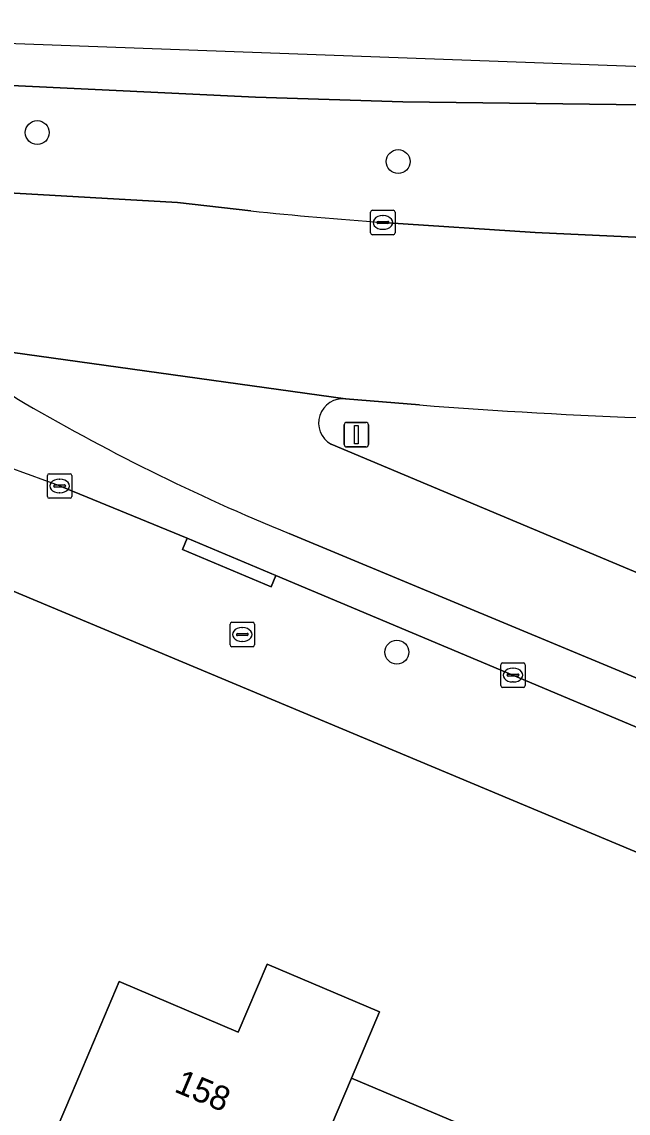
# Model space of a CAD drawing. Extents: x 162073 to 163043, y 381818 to 382561.
# Drawn here: x 162513.48 to 162538.27, y 382469.34 to 382513.97 of the extents above; entities that cross this region are included whole.
import ezdxf

# ---------------------------------------------------------------- set-up
doc = ezdxf.new("R2010")
doc.units = 0
for name, color, linetype in [('IMGEO_Boom', 7, 'Continuous'), ('IMGEO_Brandkraan', 7, 'Continuous'), ('IMGEO_Erf', 7, 'Continuous'), ('IMGEO_Fietspad_gesloten', 7, 'Continuous'), ('IMGEO_Groenvoorziening', 7, 'Continuous'), ('IMGEO_Kolk', 7, 'Continuous'), ('IMGEO_Lichtmast', 7, 'Continuous'), ('IMGEO_Pand', 7, 'Continuous'), ('IMGEO_Pand_nummerreeks', 7, 'Continuous'), ('IMGEO_Rijbaan_lokaal_gesloten', 7, 'Continuous'), ('IMGEO_Rijbaan_lokaal_open', 7, 'Continuous'), ('IMGEO_Verkeerseiland_groen', 7, 'Continuous'), ('IMGEO_Voetpad_open', 7, 'Continuous')]:
    doc.layers.add(name, color=color, linetype=linetype)

msp = doc.modelspace()

# ---------------------------------------------------------------- linework, layer by layer
at = {"layer": 'IMGEO_Boom'}
for centre in [(162514.109, 382509.442), (162528.864, 382508.257), (162528.813, 382488.194)]:
    msp.add_circle(centre, 0.489, dxfattribs=at)
at = {"layer": 'IMGEO_Brandkraan'}
for p, q in [((162521.991, 382488.49), (162521.991, 382489.342)), ((162522.066, 382489.416), (162522.918, 382489.416)), ((162522.479, 382489.196), (162522.504, 382489.196)), ((162522.992, 382489.342), (162522.992, 382488.49)), ((162522.25, 382488.91), (162522.25, 382488.922)), ((162522.688, 382488.873), (162522.29, 382488.873)), ((162522.293, 382488.959), (162522.691, 382488.959)), ((162522.502, 382488.636), (162522.477, 382488.636)), ((162522.734, 382488.922), (162522.734, 382488.91)), ((162522.918, 382488.416), (162522.066, 382488.416))]:
    msp.add_line(p, q, dxfattribs=at)
for points in [[(162521.991, 382488.49), (162521.991, 382489.342)], [(162522.066, 382489.416), (162522.918, 382489.416)], [(162522.992, 382489.342), (162522.992, 382488.49)], [(162522.918, 382488.416), (162522.066, 382488.416)]]:
    msp.add_lwpolyline(points, dxfattribs=at)
for centre, radius, start, end in [((162522.068, 382489.34), 0.0765, 91.552, 178.448), ((162522.068, 382489.34), 0.0765, 91.552, 178.448), ((162522.916, 382489.34), 0.0765, 1.552, 88.448), ((162522.916, 382489.34), 0.0765, 1.552, 88.448), ((162522.29, 382488.919), 0.0403, 85.8775, 175.7526), ((162522.287, 382488.909), 0.0366, 178.938, 274.7102), ((162522.691, 382488.916), 0.043, 264.8664, 352.4533), ((162522.695, 382488.921), 0.0386, 1.7309, 96.639), ((162522.068, 382488.492), 0.0765, 181.552, 268.448), ((162522.068, 382488.492), 0.0765, 181.552, 268.448), ((162522.916, 382488.492), 0.0765, 271.552, 358.448), ((162522.916, 382488.492), 0.0765, 271.552, 358.448)]:
    msp.add_arc(centre, radius, start, end, dxfattribs=at)
for centre, major_axis, ratio, start_param, end_param in [((162522.478, 382488.916), (-0.387, 0.002), 0.722429, 4.712389, 7.853982), ((162522.503, 382488.916), (-0.39, 0.002), 0.717154, 1.570796, 4.712389)]:
    msp.add_ellipse(centre, major_axis=major_axis, ratio=ratio, start_param=start_param, end_param=end_param, dxfattribs=at)
at = {"layer": 'IMGEO_Erf'}
for points in [[(162564.361, 382469.237), (162500, 382496.185), (162492.214, 382499.445), (162479.372, 382488.893), (162482.853, 382462.333)], [(162513.979, 382466.527), (162515.504, 382470.123), (162517.456, 382474.726), (162522.33, 382472.659), (162523.506, 382475.432), (162528.109, 382473.481), (162526.962, 382470.776), (162536.214, 382466.853)]]:
    msp.add_lwpolyline(points, dxfattribs=at)
at = {"layer": 'IMGEO_Fietspad_gesloten'}
for points in [[(162515.019, 382494.99), (162520.239, 382492.857), (162523.867, 382491.324), (162533.557, 382487.255), (162549.296, 382480.629), (162553.843, 382478.68), (162562.046, 382475.271), (162566.209, 382473.655)], [(162566.754, 382475.425), (162524.41, 382493.044)]]:
    msp.add_lwpolyline(points, dxfattribs=at)
for centre, radius, start, end in [((162376.921, 382120.599), 399.049, 69.75299, 71.58067), ((162557.485, 382573.737), 87.209, 239.53716, 247.71197)]:
    msp.add_arc(centre, radius, start, end, dxfattribs=at)
at = {"layer": 'IMGEO_Groenvoorziening'}
for points in [[(162529.739, 382498.302), (162526.719, 382498.55)], [(162526.122, 382496.703), (162540.63, 382490.602)]]:
    msp.add_lwpolyline(points, dxfattribs=at)
for centre, radius, start, end in [((162526.6, 382497.569), 0.989, 83.0633, 241.1123), ((162547.316, 382725.761), 228.137, 265.58112, 275.23655)]:
    msp.add_arc(centre, radius, start, end, dxfattribs=at)
at = {"layer": 'IMGEO_Kolk'}
for p, q in [((162527.74, 382505.34), (162527.74, 382506.192)), ((162527.815, 382506.266), (162528.667, 382506.266)), ((162528.228, 382506.046), (162528.253, 382506.046)), ((162528.741, 382506.192), (162528.741, 382505.34)), ((162527.999, 382505.76), (162527.999, 382505.772)), ((162528.437, 382505.723), (162528.039, 382505.723)), ((162528.042, 382505.809), (162528.44, 382505.809)), ((162528.483, 382505.772), (162528.483, 382505.76)), ((162528.667, 382505.266), (162527.815, 382505.266)), ((162528.251, 382505.486), (162528.226, 382505.486)), ((162514.522, 382494.564), (162514.522, 382495.416)), ((162514.597, 382495.49), (162515.449, 382495.49)), ((162515.01, 382495.27), (162515.035, 382495.27)), ((162515.523, 382495.416), (162515.523, 382494.564)), ((162514.781, 382494.984), (162514.781, 382494.996)), ((162515.219, 382494.947), (162514.821, 382494.947)), ((162514.824, 382495.033), (162515.222, 382495.033)), ((162515.265, 382494.996), (162515.265, 382494.984)), ((162515.449, 382494.49), (162514.597, 382494.49)), ((162515.033, 382494.71), (162515.008, 382494.71)), ((162533.06, 382486.828), (162533.06, 382487.68)), ((162533.135, 382487.754), (162533.987, 382487.754)), ((162534.061, 382487.68), (162534.061, 382486.828)), ((162533.319, 382487.248), (162533.319, 382487.26)), ((162533.757, 382487.211), (162533.359, 382487.211)), ((162533.362, 382487.297), (162533.76, 382487.297)), ((162533.548, 382487.534), (162533.573, 382487.534)), ((162533.803, 382487.26), (162533.803, 382487.248)), ((162533.987, 382486.754), (162533.135, 382486.754)), ((162533.571, 382486.974), (162533.546, 382486.974))]:
    msp.add_line(p, q, dxfattribs=at)
for points in [[(162527.74, 382505.34), (162527.74, 382506.192)], [(162527.815, 382506.266), (162528.667, 382506.266)], [(162528.741, 382506.192), (162528.741, 382505.34)], [(162528.667, 382505.266), (162527.815, 382505.266)], [(162514.522, 382494.564), (162514.522, 382495.416)], [(162514.597, 382495.49), (162515.449, 382495.49)], [(162515.523, 382495.416), (162515.523, 382494.564)], [(162515.449, 382494.49), (162514.597, 382494.49)], [(162533.06, 382486.828), (162533.06, 382487.68)], [(162533.135, 382487.754), (162533.987, 382487.754)], [(162534.061, 382487.68), (162534.061, 382486.828)], [(162533.987, 382486.754), (162533.135, 382486.754)]]:
    msp.add_lwpolyline(points, dxfattribs=at)
for centre, radius, start, end in [((162527.817, 382506.19), 0.0765, 91.552, 178.448), ((162527.817, 382506.19), 0.0765, 91.552, 178.448), ((162528.665, 382506.19), 0.0765, 1.552, 88.448), ((162528.665, 382506.19), 0.0765, 1.552, 88.448), ((162528.039, 382505.769), 0.0403, 85.8775, 175.7526), ((162528.036, 382505.759), 0.0366, 178.938, 274.7102), ((162528.44, 382505.766), 0.043, 264.8664, 352.4533), ((162528.444, 382505.771), 0.0386, 1.7309, 96.639), ((162527.817, 382505.342), 0.0765, 181.552, 268.448), ((162527.817, 382505.342), 0.0765, 181.552, 268.448), ((162528.665, 382505.342), 0.0765, 271.552, 358.448), ((162528.665, 382505.342), 0.0765, 271.552, 358.448), ((162514.599, 382495.414), 0.0765, 91.552, 178.448), ((162514.599, 382495.414), 0.0765, 91.552, 178.448), ((162515.447, 382495.414), 0.0765, 1.552, 88.448), ((162515.447, 382495.414), 0.0765, 1.552, 88.448), ((162514.821, 382494.993), 0.0403, 85.8775, 175.7526), ((162514.818, 382494.983), 0.0366, 178.938, 274.7102), ((162515.222, 382494.99), 0.043, 264.8664, 352.4533), ((162515.226, 382494.995), 0.0386, 1.7309, 96.639), ((162514.599, 382494.566), 0.0765, 181.552, 268.448), ((162514.599, 382494.566), 0.0765, 181.552, 268.448), ((162515.447, 382494.566), 0.0765, 271.552, 358.448), ((162515.447, 382494.566), 0.0765, 271.552, 358.448), ((162533.137, 382487.678), 0.0765, 91.552, 178.448), ((162533.137, 382487.678), 0.0765, 91.552, 178.448), ((162533.985, 382487.678), 0.0765, 1.552, 88.448), ((162533.985, 382487.678), 0.0765, 1.552, 88.448), ((162533.359, 382487.257), 0.0403, 85.8775, 175.7526), ((162533.356, 382487.247), 0.0366, 178.938, 274.7102), ((162533.76, 382487.254), 0.043, 264.8664, 352.4533), ((162533.764, 382487.259), 0.0386, 1.7309, 96.639), ((162533.137, 382486.83), 0.0765, 181.552, 268.448), ((162533.137, 382486.83), 0.0765, 181.552, 268.448), ((162533.985, 382486.83), 0.0765, 271.552, 358.448), ((162533.985, 382486.83), 0.0765, 271.552, 358.448)]:
    msp.add_arc(centre, radius, start, end, dxfattribs=at)
for centre, major_axis, ratio, start_param, end_param in [((162528.227, 382505.766), (-0.387, 0.002), 0.722429, 4.712389, 7.853982), ((162528.252, 382505.766), (-0.39, 0.002), 0.717154, 1.570796, 4.712389), ((162515.009, 382494.99), (-0.387, 0.002), 0.722429, 4.712389, 7.853982), ((162515.034, 382494.99), (-0.39, 0.002), 0.717154, 1.570796, 4.712389), ((162533.547, 382487.254), (-0.387, 0.002), 0.722429, 4.712389, 7.853982), ((162533.572, 382487.254), (-0.39, 0.002), 0.717154, 1.570796, 4.712389)]:
    msp.add_ellipse(centre, major_axis=major_axis, ratio=ratio, start_param=start_param, end_param=end_param, dxfattribs=at)
at = {"layer": 'IMGEO_Lichtmast'}
for p, q in [((162526.658, 382496.688), (162526.658, 382497.488)), ((162526.658, 382497.488), (162526.658, 382496.688)), ((162526.758, 382497.588), (162527.548, 382497.588)), ((162527.548, 382497.588), (162526.758, 382497.588)), ((162527.648, 382497.488), (162527.648, 382496.688)), ((162527.648, 382496.688), (162527.648, 382497.488)), ((162527.548, 382496.588), (162526.758, 382496.588)), ((162526.758, 382496.588), (162527.548, 382496.588))]:
    msp.add_line(p, q, dxfattribs=at)
msp.add_lwpolyline([(162527.078, 382497.463), (162527.228, 382497.463), (162527.228, 382496.713), (162527.078, 382496.713), (162527.078, 382497.463)], dxfattribs=at)
for centre, start, end in [((162526.758, 382497.488), 90, 180), ((162526.758, 382497.488), 90, 180), ((162527.548, 382497.488), 0, 90), ((162527.548, 382497.488), 360, 90), ((162526.758, 382496.688), 180, 270), ((162526.758, 382496.688), 180, 270), ((162527.548, 382496.688), 270, 0), ((162527.548, 382496.688), 270, 0)]:
    msp.add_arc(centre, 0.1, start, end, dxfattribs=at)
at = {"layer": 'IMGEO_Pand'}
for points in [[(162526.962, 382470.776), (162528.109, 382473.481), (162523.506, 382475.432), (162522.33, 382472.659), (162517.456, 382474.726), (162515.504, 382470.123), (162513.979, 382466.527), (162517.154, 382465.181), (162517.475, 382465.939), (162519.902, 382464.91), (162523.294, 382463.472), (162523.766, 382463.272)], [(162536.214, 382466.853), (162526.962, 382470.776), (162523.766, 382463.272), (162522.077, 382459.304), (162525.471, 382457.865), (162527.152, 382461.86), (162533.041, 382459.363)]]:
    msp.add_lwpolyline(points, close=True, dxfattribs=at)
at = {"layer": 'IMGEO_Rijbaan_lokaal_gesloten'}
for points in [[(163018.573, 382480.059), (162974.141, 382488.446), (162744.173, 382544.816), (162707.132, 382546.311), (162665.053, 382540.041), (162584.286, 382516.986), (162542.133, 382512.019), (162515.839, 382512.978), (162501.135, 382513.514), (162488.722, 382518.442), (162488.217, 382516.6), (162489.529, 382516.049)], [(162493.06, 382508.843), (162486.626, 382511.509), (162485.439, 382507.503), (162489.028, 382505.962), (162498.724, 382503.538), (162500, 382503.219), (162506.427, 382501.612), (162509.137, 382501.043), (162509.284, 382500.985), (162516.337, 382500), (162526.719, 382498.55), (162529.739, 382498.302)], [(162513.055, 382511.37), (162523.035, 382510.893), (162529.055, 382510.701), (162539.954, 382510.571)], [(162522.847, 382506.244), (162519.844, 382506.585), (162498.887, 382507.785)], [(162549.777, 382504.959), (162543.671, 382504.983), (162538.859, 382505.153), (162534.465, 382505.356), (162528.241, 382505.765)]]:
    msp.add_lwpolyline(points, dxfattribs=at)
for centre, radius, start, end in [((162540.559, 382675.089), 169.772, 264.01149, 265.83913), ((162547.316, 382725.761), 228.137, 265.58112, 275.23655)]:
    msp.add_arc(centre, radius, start, end, dxfattribs=at)
at = {"layer": 'IMGEO_Rijbaan_lokaal_open'}
for points in [[(162526.719, 382498.55), (162516.337, 382500), (162509.284, 382500.985), (162510.925, 382500), (162513.054, 382498.722), (162513.272, 382498.567)], [(162582.76, 382475.927), (162579.772, 382476.283), (162579.611, 382476.311), (162578.953, 382476.426), (162577.032, 382476.785), (162575.762, 382477.02), (162570.894, 382478.266), (162569.216, 382478.792), (162567.234, 382479.449), (162563.243, 382481.094), (162562.882, 382481.243), (162561.209, 382481.902), (162561.053, 382481.968), (162560.115, 382482.367), (162557.62, 382483.429), (162547.286, 382487.786), (162540.63, 382490.602), (162526.122, 382496.703)], [(162524.41, 382493.044), (162566.754, 382475.425)]]:
    msp.add_lwpolyline(points, dxfattribs=at)
for centre, radius, start, end in [((162557.485, 382573.737), 87.209, 239.53716, 247.71197), ((162526.6, 382497.569), 0.989, 83.0633, 241.1123)]:
    msp.add_arc(centre, radius, start, end, dxfattribs=at)
at = {"layer": 'IMGEO_Verkeerseiland_groen'}
for points in [[(162539.954, 382510.571), (162529.055, 382510.701), (162523.035, 382510.893), (162513.055, 382511.37)], [(162498.887, 382507.785), (162519.844, 382506.585), (162522.847, 382506.244)], [(162528.241, 382505.765), (162534.465, 382505.356), (162538.859, 382505.153), (162543.671, 382504.983), (162549.777, 382504.959)]]:
    msp.add_lwpolyline(points, dxfattribs=at)
msp.add_arc((162540.559, 382675.089), 169.772, 264.01149, 265.83913, dxfattribs=at)
at = {"layer": 'IMGEO_Voetpad_open'}
for points in [[(162483.778, 382503.442), (162492.214, 382499.445), (162500, 382496.185), (162564.361, 382469.237)], [(162566.209, 382473.655), (162562.046, 382475.271), (162561.855, 382474.81), (162553.652, 382478.219), (162553.843, 382478.68), (162549.296, 382480.629), (162533.557, 382487.255), (162523.867, 382491.324), (162523.673, 382490.864), (162520.045, 382492.397), (162520.239, 382492.857), (162515.019, 382494.99)]]:
    msp.add_lwpolyline(points, dxfattribs=at)
msp.add_lwpolyline([(162523.867, 382491.324), (162520.239, 382492.857), (162520.045, 382492.397), (162523.673, 382490.864)], close=True, dxfattribs=at)
msp.add_arc((162376.921, 382120.599), 399.049, 69.75299, 71.58067, dxfattribs=at)

# ---------------------------------------------------------------- texts
at = {"layer": 'IMGEO_Pand_nummerreeks'}
msp.add_text('158', height=1, rotation=337.1619, dxfattribs=at).set_placement((162519.667, 382470.236))

doc.saveas('drawing.dxf')
